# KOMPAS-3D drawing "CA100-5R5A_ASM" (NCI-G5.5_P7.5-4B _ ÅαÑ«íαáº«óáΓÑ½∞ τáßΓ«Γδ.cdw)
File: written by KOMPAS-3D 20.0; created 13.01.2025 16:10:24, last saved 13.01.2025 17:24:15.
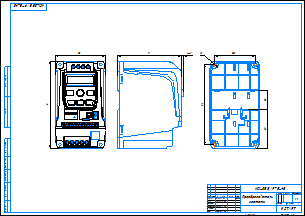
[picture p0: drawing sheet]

Sheet 1: A2, landscape

Document properties: Автор: admin; Полное имя файла: P:\INSTART\Технический отдел\ОР\Прочие задачи\КД на номенклатурный ряд\КД на типоразмеры ПЧ\NCI\NCI-G5.5_P7.5-4B\NCI-G5.5_P7.5-4B _ Преобразователь частоты.cdw

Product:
- Part/product: CA100-5R5A_ASM
    Масса: 7.13181
    Комментарий: NOT SPECIFIED
  - Component [detail]: AA  | Масса: 1.44663; source file: C:\Уралов Работа\Уралов (локальная)\ПЧ\! Китай 3Д-модель NCI\NCI 4.0-7.5 4B\AA.m3d
  - Component [detail]: CA100-2R2A-SJ-04  | Масса: 0.00516082; source file: C:\Уралов Работа\Уралов (локальная)\ПЧ\! Китай 3Д-модель NCI\NCI 4.0-7.5 4B\CA100-2R2A-SJ-04.m3d
  - Component [assembly]: JIANPAN99_ASM_ASM  | Масса: 0.107178; Комментарий: NOT SPECIFIED; source file: C:\Уралов Работа\Уралов (локальная)\ПЧ\! Китай 3Д-модель NCI\NCI 4.0-7.5 4B\JIANPAN99_ASM_ASM.a3d
  - Component [assembly]: CA100-5R5A-SJ_ASM  | Масса: 1.6976; Комментарий: NOT SPECIFIED; source file: C:\Уралов Работа\Уралов (локальная)\ПЧ\! Китай 3Д-модель NCI\NCI 4.0-7.5 4B\CA100-5R5A-SJ_ASM.a3d
  - Component [assembly]: PCB_ASM  | Масса: 1.9346; source file: C:\Уралов Работа\Уралов (локальная)\ПЧ\! Китай 3Д-модель NCI\NCI 4.0-7.5 4B\PCB_ASM.a3d
  - Component [assembly]: QJ_ASM  | Масса: 0.208727; source file: C:\Уралов Работа\Уралов (локальная)\ПЧ\! Китай 3Д-модель NCI\NCI 4.0-7.5 4B\QJ_ASM.a3d
  - Component [detail]: CA100-4R0A-SR-01  | Масса: 0.923365; source file: C:\Уралов Работа\Уралов (локальная)\ПЧ\! Китай 3Д-модель NCI\NCI 4.0-7.5 4B\CA100-4R0A-SR-01.m3d
  - Component [detail]: CA100-5R5A-SR-01  | Масса: 0.808548; source file: C:\Уралов Работа\Уралов (локальная)\ПЧ\! Китай 3Д-модель NCI\NCI 4.0-7.5 4B\CA100-5R5A-SR-01.m3d

Title block, sheet 1: Наименование: Преобразователь / частоты; designation: NCI-G5.5/P7.5-4B; Количество листов документа: 1; organisation: INSTART; cell 10: Согласовано; Форматы листов документа: A2; stored path: P:\INSTART\Технический отдел\ОР\Прочие задачи\КД на номенклатурный ряд\КД на типоразмеры ПЧ\NCI\NCI-G4.0_P5.5-4B\NCI-G4.0_P5.5-4B _ Преобразователь частоты.cdw; Разработал: Уралов Д.А.; Проверил: Андреев Н.В.; Подписал: Смелков Ж.Е.; Утвердил: Ефремов И.Н.; Разработал, date: 13.01.25

Views: Вид 1, Проекционный вид 2
Referenced files in C:\Уралов Работа\Уралов (локальная)\ПЧ\! Китай 3Д-модель NCI\NCI 4.0-7.5 4B\: CA100-4R0A-SR-01.m3d, CA100-5R5A-SR-01.m3d, 6025.m3d, QJ_ASM.a3d, QDB.m3d, DRI.m3d, 6912184100XX_MASS.m3d, 6912184100XX_PIN.m3d, 6912184100XX_VIS.m3d, 691218410003.m3d, ASSEM1_ASM.a3d, EU5-03-952_ASM.a3d, QDB_ASM.a3d, 2R2-CM.m3d, EU1_5-14-5_08-00_1_.m3d, LED.m3d, DWQ_2.m3d, ANJIAN.m3d, BM.m3d, 485.m3d, 2R2-CM_ASM.a3d, DRB.m3d, DR.m3d, DRB_ASM.a3d, PCB_ASM.a3d, CA100-5R5A-SJ-01.m3d, CA100-5R5A-SJ-02.m3d, CA100-5R5A-SJ-01-.m3d, CA100-5R5A-SJ_ASM.a3d, CA100-2R2A-SJ-05_45.m3d, CA100-2R2A-SJ-06_23.m3d, CA100-2R2A-SJ-03_22.m3d, JIANPAN99_ASM_17_ASM.a3d, JIANPAN99_ASM_ASM.a3d, CA100-2R2A-SJ-04.m3d, AA.m3d, NCI 4.0-7.5 4B.a3d
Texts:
  CA100-4R0A-SR-01
  CA100-4R0A-SR-01 CA100-4R0A-SR-01
  CA100-5R5A-SR-01
  CA100-5R5A-SR-01 CA100-5R5A-SR-01
  QJ_ASM QJ_ASM
  QDB
  QDB QDB
  DRI
  DRI DRI
  6912184100XX_MASS 6912184100XX_MASS
  6912184100XX_PIN 6912184100XX_PIN
  6912184100XX_VIS 6912184100XX_VIS
  ASSEM1_ASM ASSEM1_ASM
  EU5-03-952_ASM
  EU5-03-952_ASM EU5-03-952_ASM
  QDB_ASM QDB_ASM
  EU1_5-14-5_08-00_1_
  EU1_5-14-5_08-00_1_ EU1_5-14-5_08-00_1_
  LED
  LED LED
  DWQ_2 DWQ_2
  ANJIAN
  ANJIAN ANJIAN
  BM BM
  DRB
  DRB DRB
  DR DR
  DRB_ASM DRB_ASM
  PCB_ASM PCB_ASM
  CA100-5R5A-SJ-01
  CA100-5R5A-SJ-01 CA100-5R5A-SJ-01
  CA100-5R5A-SJ-02
  CA100-5R5A-SJ-02 CA100-5R5A-SJ-02
  CA100-5R5A-SJ-01-
  CA100-5R5A-SJ-01- CA100-5R5A-SJ-01-
  CA100-5R5A-SJ_ASM
  CA100-5R5A-SJ_ASM CA100-5R5A-SJ_ASM
  CA100-2R2A-SJ-05_45
  CA100-2R2A-SJ-05_45 CA100-2R2A-SJ-05_45
  CA100-2R2A-SJ-06_23
  CA100-2R2A-SJ-06_23 CA100-2R2A-SJ-06_23
  CA100-2R2A-SJ-03_22
  CA100-2R2A-SJ-03_22 CA100-2R2A-SJ-03_22
  JIANPAN99_ASM_17_ASM JIANPAN99_ASM_17_ASM
  JIANPAN99_ASM_ASM JIANPAN99_ASM_ASM
  Поверхности
  CA100-2R2A-SJ-04
  CA100-2R2A-SJ-04 CA100-2R2A-SJ-04
  AA AA
  CA100-5R5A_ASM
  CA100-5R5A_ASM CA100-5R5A_ASM
Dimensions and other numbers on the sheet: 4±1; 1:1; 1; 13.01.25; 6025; 6025 6025; 2R2-CM; 2R2-CM 2R2-CM; 485; 485 485; 2R2-CM_ASM; 2R2-CM_ASM 2R2-CM_ASM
